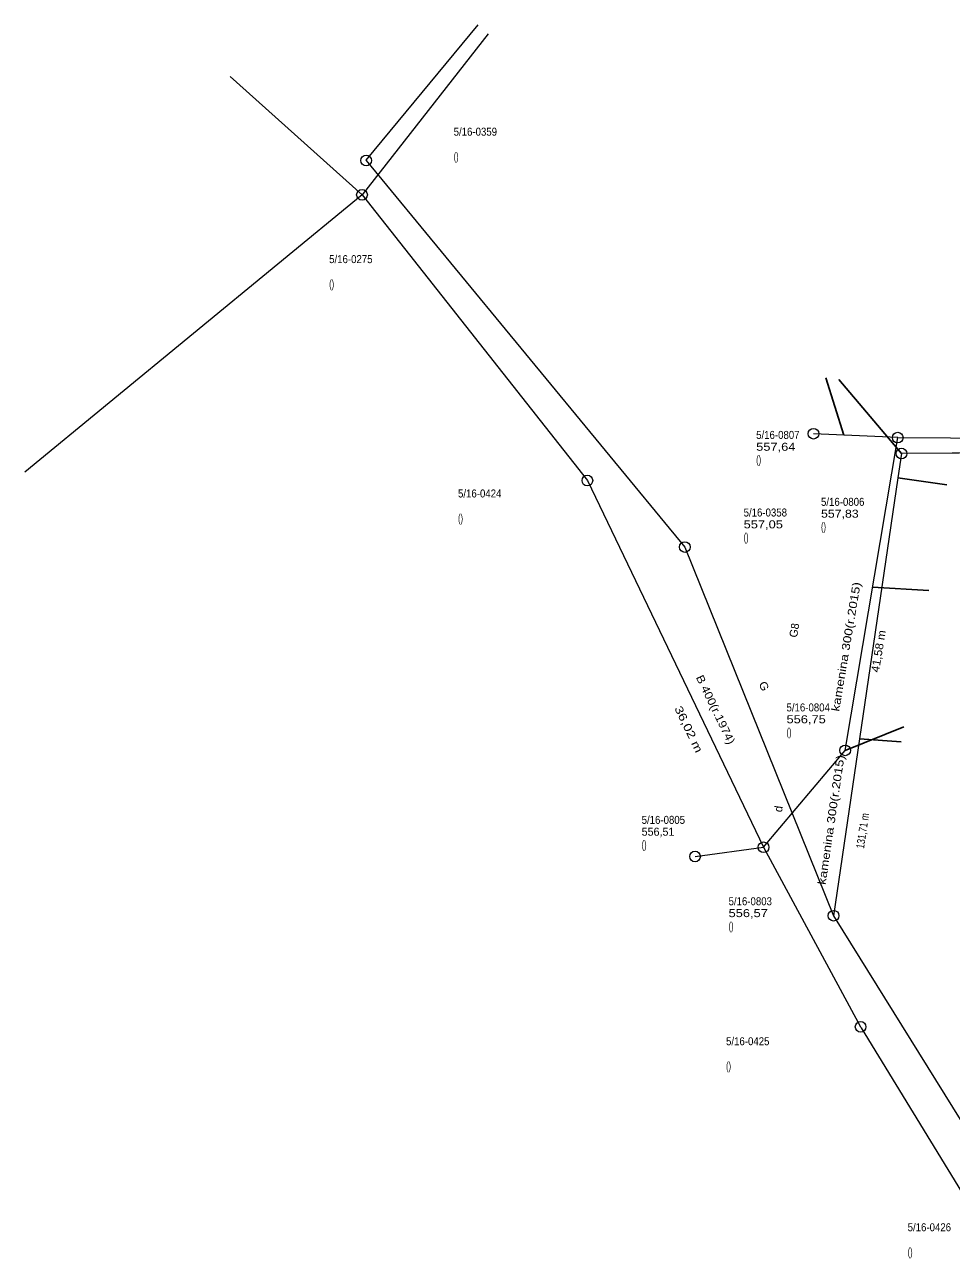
# Model space of a CAD drawing. Extents: x -710854 to -709799, y -1117012 to -1115891.
# Drawn here: x -710568.8 to -710481.9, y -1116463.6 to -1116348 of the extents above; entities that cross this region are included whole.
import ezdxf
from ezdxf.enums import TextEntityAlignment as Align

# ---------------------------------------------------------------- set-up
doc = ezdxf.new("R2010")
doc.units = 0
doc.header["$LTSCALE"] = 0.3
for name, color, linetype, lineweight in [('35', 7, 'Continuous', 25), ('36', 7, 'Continuous', 13), ('37', 7, 'Continuous', 13), ('38', 7, 'Continuous', 13), ('44', 7, 'Continuous', 13)]:
    doc.layers.add(name, color=color, linetype=linetype, lineweight=lineweight)
doc.layers.add('48', color=7, linetype='Continuous')

msp = doc.modelspace()

# ---------------------------------------------------------------- linework, layer by layer
at = {"layer": '35'}
for p, q in [((-710491.99, -1116386.43), (-710493.68, -1116381.05)), ((-710486.59, -1116388.16), (-710492.48, -1116381.22)), ((-710486.926, -1116390.441), (-710482.363, -1116391.1)), ((-710489.3, -1116400.67), (-710484.04, -1116400.98)), ((-710491.87, -1116415.97), (-710486.37, -1116413.75)), ((-710490.519, -1116414.88), (-710486.64, -1116415.16))]:
    msp.add_line(p, q, dxfattribs=at)
at = {"layer": '36'}
msp.add_line((-710536.766, -1116360.698), (-710506.893, -1116396.918), dxfattribs=at)
for points in [[(-710526.302, -1116347.973), (-710526.307, -1116347.978), (-710536.79, -1116360.669), (-710536.766, -1116360.698)], [(-710486.59, -1116388.16), (-710486.926, -1116390.441), (-710490.519, -1116414.88), (-710492.96, -1116431.46)], [(-710450.53, -1116387.94), (-710457.99, -1116387.99), (-710468.56, -1116388.05), (-710476.59, -1116388.1), (-710481.19, -1116388.13), (-710481.86, -1116388.13), (-710486.59, -1116388.16)], [(-710506.893, -1116396.918), (-710492.96, -1116431.46), (-710474.57, -1116461.041)]]:
    msp.add_lwpolyline(points, dxfattribs=at)
at = {"layer": '37'}
for p, q in [((-710486.95, -1116386.67), (-710494.84, -1116386.3)), ((-710505.94, -1116425.91), (-710499.52, -1116425.05))]:
    msp.add_line(p, q, dxfattribs=at)
for points in [[(-710499.52, -1116425.05), (-710491.87, -1116415.97), (-710486.95, -1116386.67)], [(-710486.95, -1116386.67), (-710452.42, -1116386.87), (-710433.11, -1116388.59), (-710410.14, -1116393.63)]]:
    msp.add_lwpolyline(points, dxfattribs=at)
at = {"layer": '38'}
for p, q in [((-710525.32, -1116348.82), (-710537.15, -1116363.92)), ((-710537.15, -1116363.92), (-710568.76, -1116389.91)), ((-710516.03, -1116390.69), (-710499.52, -1116425.05)), ((-710499.52, -1116425.05), (-710490.428, -1116441.873))]:
    msp.add_line(p, q, dxfattribs=at)
for points in [[(-710549.495, -1116352.824), (-710537.15, -1116363.92), (-710516.03, -1116390.69)], [(-710490.428, -1116441.873), (-710490.41, -1116441.91), (-710490.378, -1116441.962), (-710479.01, -1116460.54)]]:
    msp.add_lwpolyline(points, dxfattribs=at)
at = {"layer": '44'}
for centre in [(-710536.766, -1116360.698), (-710537.15, -1116363.92), (-710494.84, -1116386.3), (-710486.95, -1116386.67), (-710486.59, -1116388.16), (-710516.03, -1116390.69), (-710506.893, -1116396.918), (-710491.87, -1116415.97), (-710499.52, -1116425.05), (-710505.94, -1116425.91), (-710492.96, -1116431.46), (-710490.428, -1116441.873)]:
    msp.add_circle(centre, 0.5, dxfattribs=at)

# ---------------------------------------------------------------- texts
at = {"layer": '48'}
for s, width, p in [('5/16-0359', 0.9, (-710528.562, -1116358.376)), ('()', 0.7, (-710528.562, -1116360.686)), ('5/16-0275', 0.9, (-710540.228, -1116370.316)), ('()', 0.7, (-710540.228, -1116372.626)), ('5/16-0807', 0.9, (-710500.215, -1116386.788)), ('557,64 ', 1.2, (-710500.215, -1116387.898)), ('()', 0.7, (-710500.215, -1116389.098)), ('5/16-0424', 0.9, (-710528.151, -1116392.274)), ('5/16-0806', 0.9, (-710494.138, -1116393.058)), ('5/16-0358', 0.9, (-710501.389, -1116394.058)), ('557,83 ', 1.15, (-710494.138, -1116394.168)), ('()', 0.7, (-710528.151, -1116394.584)), ('557,05 ', 1.2, (-710501.389, -1116395.168)), ('()', 0.7, (-710494.138, -1116395.368)), ('()', 0.7, (-710501.389, -1116396.368)), ('5/16-0804', 0.9, (-710497.37, -1116412.322)), ('556,75 ', 1.2, (-710497.37, -1116413.432)), ('()', 0.7, (-710497.37, -1116414.632)), ('5/16-0805', 0.9, (-710510.945, -1116422.858)), ('()', 0.7, (-710510.945, -1116425.168)), ('5/16-0803', 0.9, (-710502.8, -1116430.486)), ('556,57 ', 1.2, (-710502.8, -1116431.596)), ('()', 0.7, (-710502.8, -1116432.796)), ('5/16-0425', 0.9, (-710503.036, -1116443.602)), ('()', 0.7, (-710503.036, -1116445.912)), ('5/16-0426', 0.9, (-710486.018, -1116461.031)), ('()', 0.7, (-710486.018, -1116463.341))]:
    msp.add_text(s, height=0.75, dxfattribs=dict(at, width=width)).set_placement(p)
for s, rotation, width, p in [('kamenina 300(r.2015)', 80.47, 1.25, (-710491.4254, -1116406.3176)), ('41,58 m', 80.47, 1.1, (-710488.3831, -1116406.7391)), ('B 400(r.1974)', 295.66, 1.15, (-710504.3543, -1116412.3111)), ('G', 295.66, 1.1, (-710499.8169, -1116410.1151)), ('36,02 m', 295.66, 1.3, (-710506.8762, -1116414.1516)), ('kamenina 300(r.2015)', 81.62, 1.25, (-710492.8179, -1116422.5302)), ('d', 81.62, 1.05, (-710497.7613, -1116421.5092)), ('131,71 m', 81.62, 0.8, (-710489.8662, -1116423.5642))]:
    msp.add_text(s, height=0.75, rotation=rotation, dxfattribs=dict(at, width=width)).set_placement(p, align=Align.CENTER)
msp.add_text('G8', height=0.75, rotation=80.47, dxfattribs=at).set_placement((-710496.2779, -1116404.7821), align=Align.CENTER)
msp.add_text('556,51 ', height=0.75, dxfattribs=at).set_placement((-710510.945, -1116423.968))

doc.saveas('drawing.dxf')
